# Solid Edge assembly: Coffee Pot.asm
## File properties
Author: rkriggs
Template: Sync Iso Assembly.asm
Last saved by: plm
Revision: 372
Application: Solid Edge
major_rev: A
圖檔名稱: Coffee Pot
圖檔編號: Coffee Pot
generation: 1
id: 134BC61CFA65427F9F326C74BE96959C
classification: Mechanical/Assembly
authoring_tool: Solid Edge
thumbnail: vault:///?fileId=6C52858E738A4FBE8B74D82351D07220
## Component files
Coffee Pot.par
Strap Handle.par
handle.par
strainer.asm
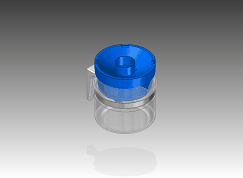
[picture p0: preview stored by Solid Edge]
